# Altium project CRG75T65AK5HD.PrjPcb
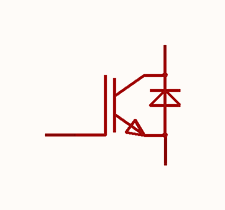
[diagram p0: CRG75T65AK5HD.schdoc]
1 sheet, 1 parts. Net scope: global (net labels, ports and power ports of the same name join across sheets).

## Sheet CRG75T65AK5HD.schdoc
size 127 x 101 mm

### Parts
Q?  crg75t65ak5hd  [TO-247-3_L15.9-W5.0-P5.44-L]  (value not drawn)

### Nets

Not connected (* = marked no-connect by the designer): Q? 1(G) 2(C) 3(E)

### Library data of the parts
Q? = crg75t65ak5hd: IGBT类型:FS(场截止);耗散功率(Pd):468W;集射极击穿电压(Vces):650V;集电极电流(Ic):75A;; Manufacturer: CRMICRO(华润微); AddInBom: yes; ModelId: 06d11a66e67643458860efec572770e6; ModelTransform: 625.983,196.85,0,0,0,0,0,5.906,-196.85; Pd - Power Dissipation: 468W; Collector-Emitter Breakdown Voltage (Vces): 650V; Current - Collector(Ic): 75A; Current - Collector Pulsed (Icm): 300A; Vce Saturation(VCE(sat)): 1.65V; Gate-Emitter Threshold Voltage (Vge(th)@Ic): 3.5V@250uA; Gate Charge(Qg): 173nC@15V; Input Capacitance(Cies): 5.477nF; Output Capacitance(Coes): 278pF; Reverse Transfer Capacitance (Cres): 30pF; Td(on): 120ns; Td(off): 355ns; Turn-On Energy (Eon): 4.95mJ; Switching Energy(Eoff): 2.17mJ; Reverse Recovery Time(trr): 59ns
